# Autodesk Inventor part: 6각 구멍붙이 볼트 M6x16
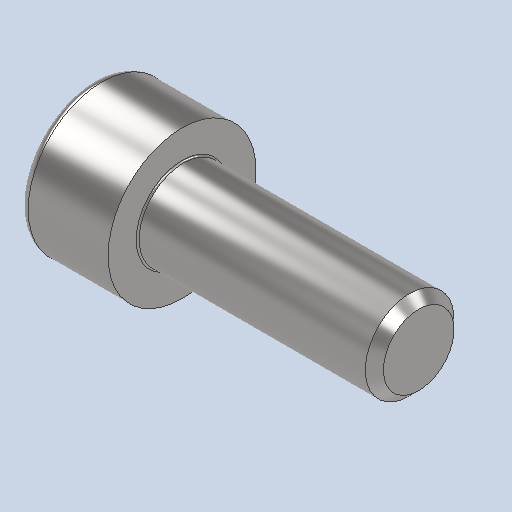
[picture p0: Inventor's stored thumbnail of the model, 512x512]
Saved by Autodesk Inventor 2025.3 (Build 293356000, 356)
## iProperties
Created: 2025-10
Part Number: 6각 구멍붙이 볼트 M6x16
Material: 강철, 연강
Description: 6각머리 태핑 나사
Document SubType Name: Modeling
Designer: PC-13
Density: 7.85 g/cm^3
Appearance: 기본값
Author: jhkim
Sending System: Autodesk Inventor 2026
Preprocessor: ST-DEVELOPER v20.1
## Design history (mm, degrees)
feature "Solid1"
node "솔리드1"
